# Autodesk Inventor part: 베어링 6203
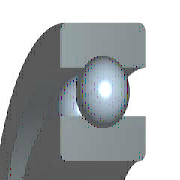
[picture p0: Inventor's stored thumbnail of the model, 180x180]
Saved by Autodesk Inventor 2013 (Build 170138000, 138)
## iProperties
IsCustomPart: 1
Created: 2015-09
Part Number: 베어링 6203
Material: 강철, 연강
Description: 깊은 그루브 볼 베어링
Document SubType Name: Modeling
Standard: KS B 2023
Standards Organization: KS
Language: ko-KR
Size Designation: 6203 - 17 x 40 x 12
Categories: <MemberInstance><Categories><Category DisplayName="샤프트 부품" InternalName="7f7aeb1f-a693-4053-b835-cee3144e0d98" Mnemonic="SHFT"><Category DisplayName="베어링" Inter
Density: 7.86 g/cm^3
Mass: 64.9809 g
Surface Area: 64.3582 cm^2
Volume: 8.26729 cm^3
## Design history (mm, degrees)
sketch "스케치" dims "d0" = 5.98 (= -0.26 x WD + 0.26 x BD)
  geometry: L1 (3.01, 14.25)-(8.99, 14.25); L2 (6, 14.25)-(6, 11.26); L3 (6, 14.25)-(6, 17.24); L4 (3.778, 12.249)-(0, 12.249); L5 (0, 8.5)-(12, 8.5); L6 (3.778, 16.251)-(0, 16.251); L7 (0, 20)-(12, 20); L8 (12, 8.5)-(12, 12.249); L9 (8.222, 12.249)-(12, 12.249); L10 (8.222, 16.251)-(12, 16.251); L11 (12, 20)-(12, 16.251); L12 (-1.4, 0)-(8.4, 0) reference; L13 (0, -0.3)-(0, 5.3) reference
  constraints: 22 end point, 4 point on line, 2 collinear, 2 perpendicular, 2 symmetric about line, 1 midpoint, 1 parallel, 14 other
  dimensions: "d9" = 17 diameter of L5 L12 (= WD); "d11" = 40 diameter of L7 L12 (= BD); "d12" = 12 distance between parallel lines of L8 L13 (= KB); "d13" = 24.498 diameter of L9 L12 (= 0.326 x BD + 0.674 x WD)
revolve "본체" stored, may be unused: angle "d6" = 90 deg
revolve "볼" stored, may be unused: angle "d7" = 90 deg
pattern_circular "IDS_ARRAYBALL[SIMPL:T]" dims angle "d3" = 360 deg
body "Solid1"
fillet "모깎기1" dims "d1" = 0.6 (= KRS)
other parameters: "WD" = 17 [user parameter; used in 5 equation terms], "BD" = 40 [user parameter; used in 5 equation terms], "KB" = 12 [user parameter; used in 1 equation term], "KRS" = 0.6 [user parameter; used in 1 equation term], "d4" = 0, "d5" = 0, "d8" = 0, "d14" = 0, "d15" = 0, "BBA" = 0 [user parameter], "BC0" = 4750000 [user parameter], "BC" = 9560000 [user parameter], "WR" = 8.5 (= 0.5 x WD) [user parameter]
